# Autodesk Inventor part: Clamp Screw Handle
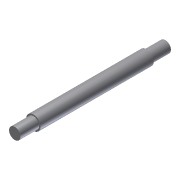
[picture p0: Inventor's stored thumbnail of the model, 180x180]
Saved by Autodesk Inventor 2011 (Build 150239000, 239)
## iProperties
Shininess: 77.0
Length Units: 11269
Angle Units: 11279
Time Units: 11290
Mass Units: 11283
Length Display Precision: 3
Angle Display Precision: 2
Compacted: True
Created: 2002-02
Part Number: Clamp Screw Handle
Document SubType Name: Modeling
Designer: ***
Density: 1 g/cm^3
Mass: 7.51155 g
Surface Area: 32.9239 cm^2
Volume: 7.51155 cm^3
Density: 0.0
Volumn: 0.0
Area: 0.0
PropertySet Name: Model Information
Control State: 0
Master: False
Checked Out: False
Author: ***
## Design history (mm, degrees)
sketch "Sketch1"
  geometry: L1 (0, 105)-(4, 105); L2 (4, 105)-(4, 92); L3 (4, 92)-(5, 92); L4 (5, 92)-(5, 13); L5 (5, 13)-(4, 13); L6 (4, 13)-(4, 0); L7 (4, 0)-(0, 0); L8 (0, 0)-(0, 105)
  constraints: 16 end point, 5 parallel, 2 equal length, 1 collinear, 1 horizontal, 1 perpendicular
  dimensions: "d0" = 10 diameter of L4 L8; "d1" = 8 diameter of L2 L8; "d2" = 13 distance of L1.end L2.end; "d3" = 79 distance of L3.end L4.end
revolve "Revolution1" sketch "Sketch1" stored, may be unused: angle "d4" = 90 deg
body "Solid1"
